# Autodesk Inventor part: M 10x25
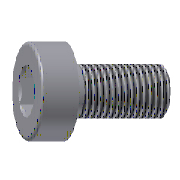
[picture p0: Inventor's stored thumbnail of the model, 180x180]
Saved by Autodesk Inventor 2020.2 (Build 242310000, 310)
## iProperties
Manager: www.cadconsulting.pl
Company: Fabian Stasiak CAD Consulting
Created: 2014-02
Part Number: M 10x25
Material: Stal, miękka
Description: Socket Head Cap Screw DIN 912 - 12.9
Document SubType Name: Modeling
Designer: F.Stasiak
Standard Revision: 1
Manufacturer: DME
Language: pl-PL
Size Designation: 10x25
Categories: <MemberInstance><Categories><Category DisplayName="Forma wtryskowa" InternalName="349578f2-f4d4-4954-8c09-8e99297a61c0" Mnemonic="MOLD"><Category DisplayName="C
Mass: 0.133121 g
Surface Area: 2.01441 cm^2
Volume: 0.133121 cm^3
Density: 7.85 g/cm^3
Appearance: Częściowo polerowana
Catalog Web Link: www.expertbooks.pl
IsCustomPart: 0
Author: F.Stasiak
Subject: Zbiór ćwiczeń. Autodesk Inventor 2020. Kurs Professional
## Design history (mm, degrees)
sketch "Sketch1"
  geometry: L1 (0, -32)-(0, 17) reference; L2 (4.619, 10)-(8, 10); L3 (8, 10)-(8, 0); L4 (8, 0)-(5, 0); L5 (5, 0)-(5, -25); L6 (5, -25)-(0, -25); L7 (0, 2.597)-(0, -25); L8 (0, 2.597)-(4, 5); L9 (4, 5)-(4, 9.381); L10 (4, 9.381)-(4.619, 10); 1 further point
  constraints: 18 end point, 4 vertical, 3 horizontal, 2 point on line
  dimensions: "d0" = 16 diameter of L3 L1 (= dk); "d1" = 10 distance between parallel lines of L4 L2 (= k); "d2" = 10 diameter of L5 L1 (= d); "d3" = 25 distance between parallel lines of L6 L4 (= L); "d4" = 59 deg angle of L1 L8; "d5" = 45 deg angle of L1 L10; "d6" = 8 diameter of L9 L1 (= sw); "d7" = 9.2376 diameter of L2.start L1 (= 1.1547 x sw); "d8" = 5 distance from line of L8.end L2 (= t)
revolve "Revolution1" sketch "Sketch1" stored, may be unused: angle "d44" = 90 deg
sketch "Sketch2"
  geometry: L1 (0, 4.619)-(4, 2.309); L2 (4, 2.309)-(4, -2.309); L3 (4, -2.309)-(0, -4.619); L4 (0, -4.619)-(-4, -2.309); L5 (-4, -2.309)-(-4, 2.309); L6 (-4, 2.309)-(0, 4.619); 3 further points
  constraints: 12 end point, 2 vertical alignment, 1 coincident, 14 other
extrude "Extrusion1" cut sketch "Sketch2" taper "d9" = 0 deg; stored distance "d45" = 10
thread "Thread1" dims "d10" = 25 (= b), "d11" = 0
chamfer "Chamfer1" distance "d12" = 0.75 (= 0.5 x P); stored, may be unused: second distance "d50" = 2, angle "d51" = 45 deg
fillet "Fillet1" dims "d13" = 0.75 (= 0.5 x P)
body "Solid1"
other parameters: "d" = 10 [user parameter; used in 1 equation term], "L" = 25 [user parameter; used in 1 equation term], "dk" = 16 [user parameter; used in 1 equation term], "b" = 25 [user parameter; used in 1 equation term], "k" = 10 [user parameter; used in 1 equation term], "sw" = 8 [user parameter; used in 2 equation terms], "t" = 5 [user parameter; used in 1 equation term], "P" = 1.5 [user parameter; used in 2 equation terms], "d14" = 0, "d15" = 0, "d55" = 0
